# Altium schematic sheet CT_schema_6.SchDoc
size 521 x 498 mm
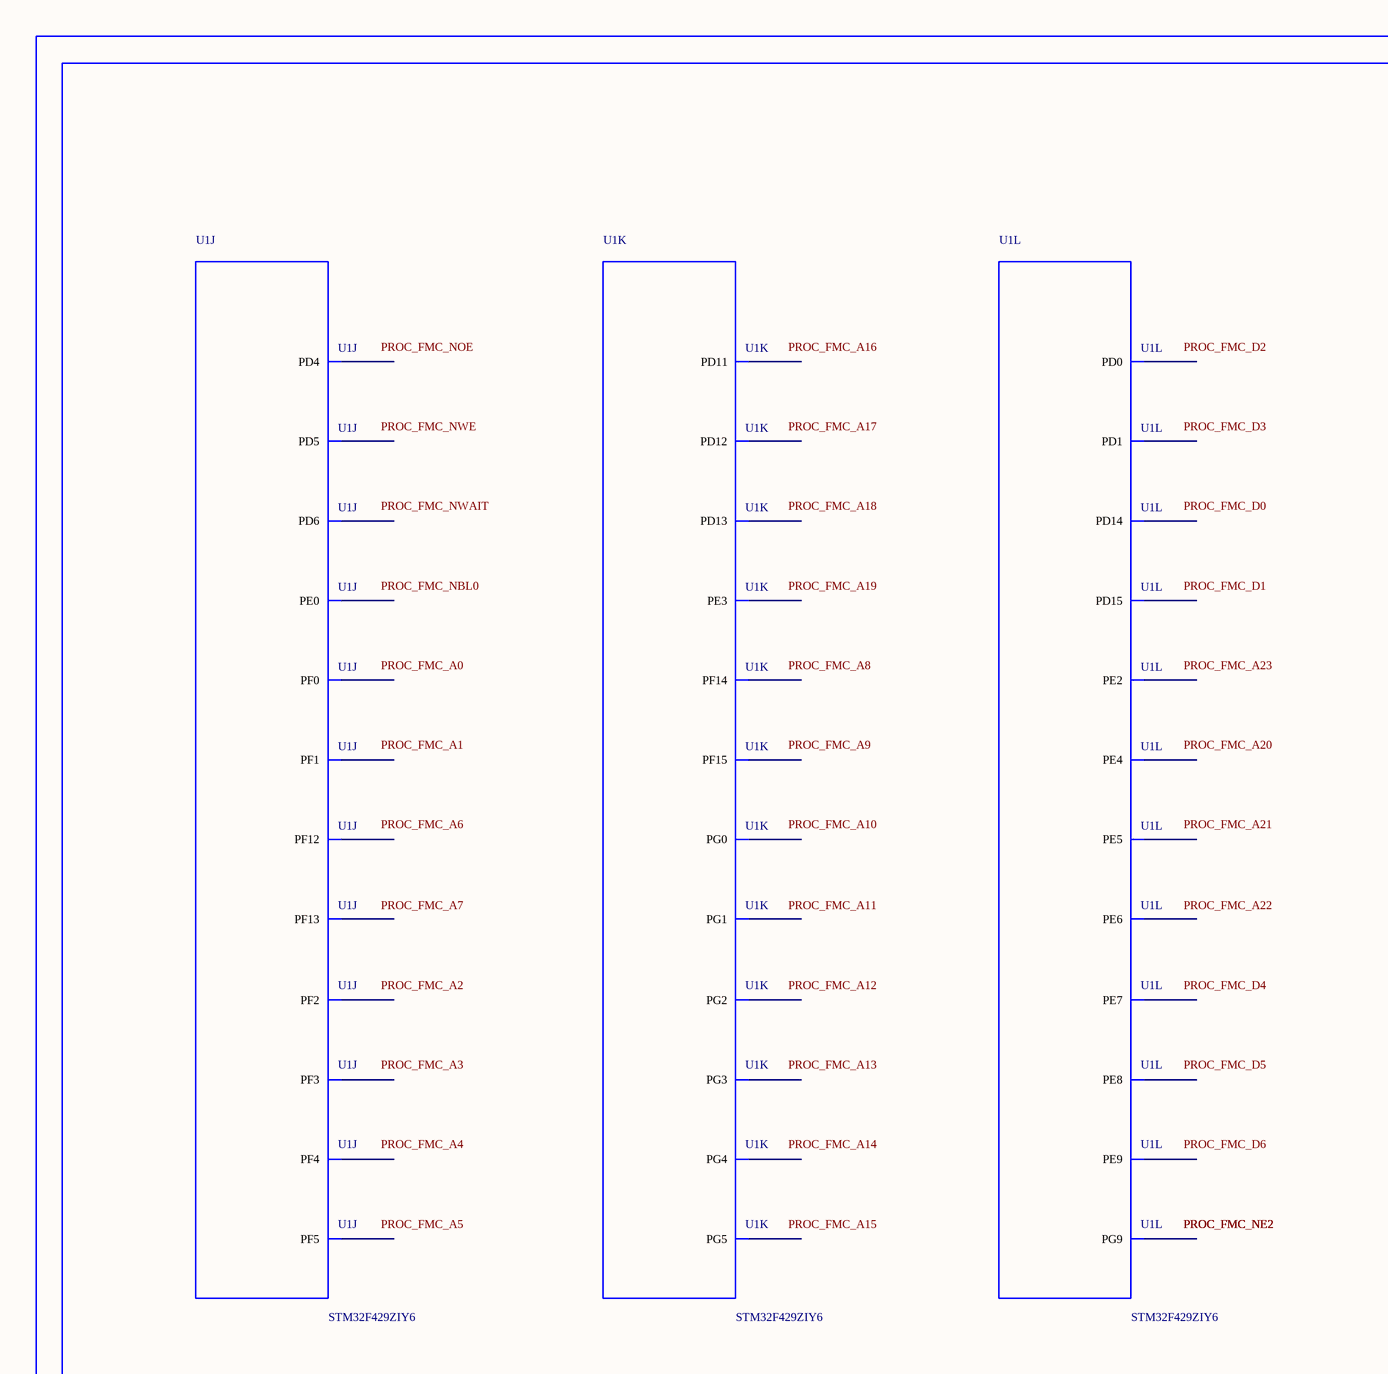
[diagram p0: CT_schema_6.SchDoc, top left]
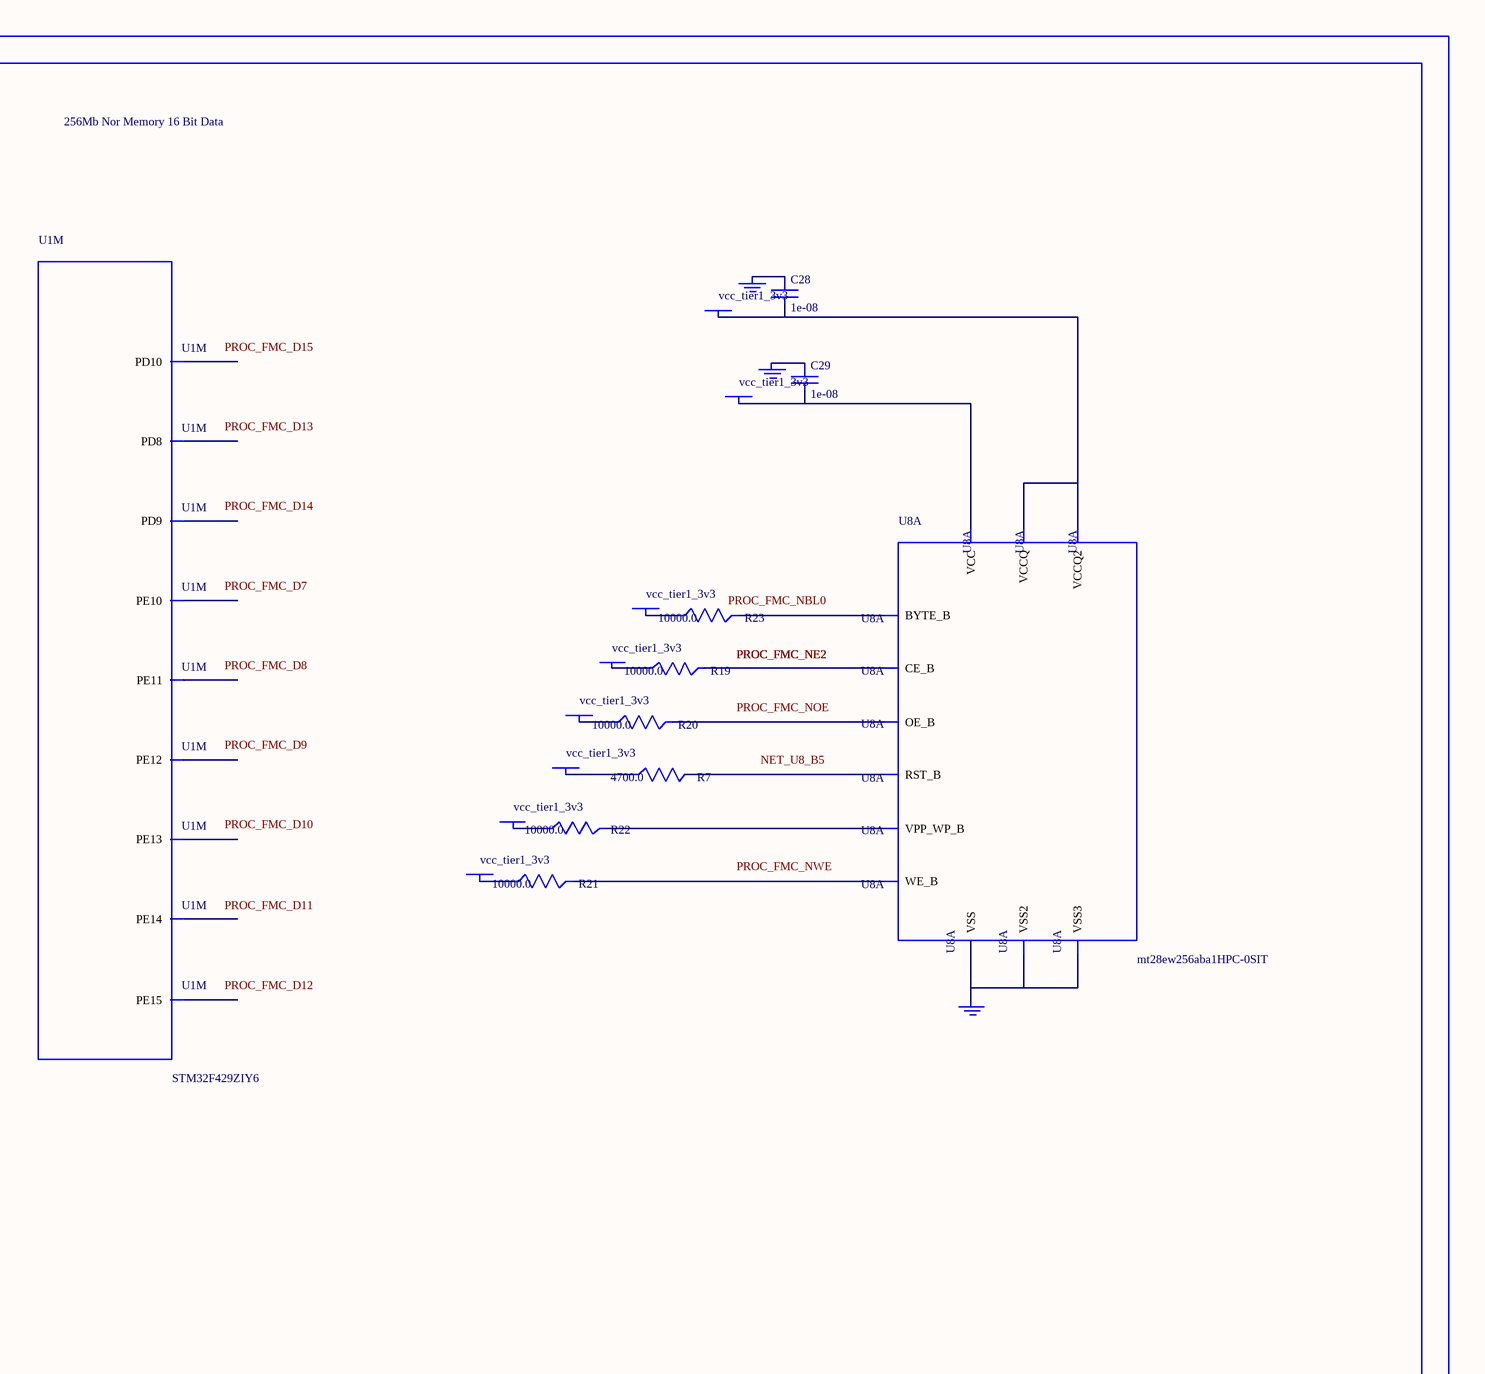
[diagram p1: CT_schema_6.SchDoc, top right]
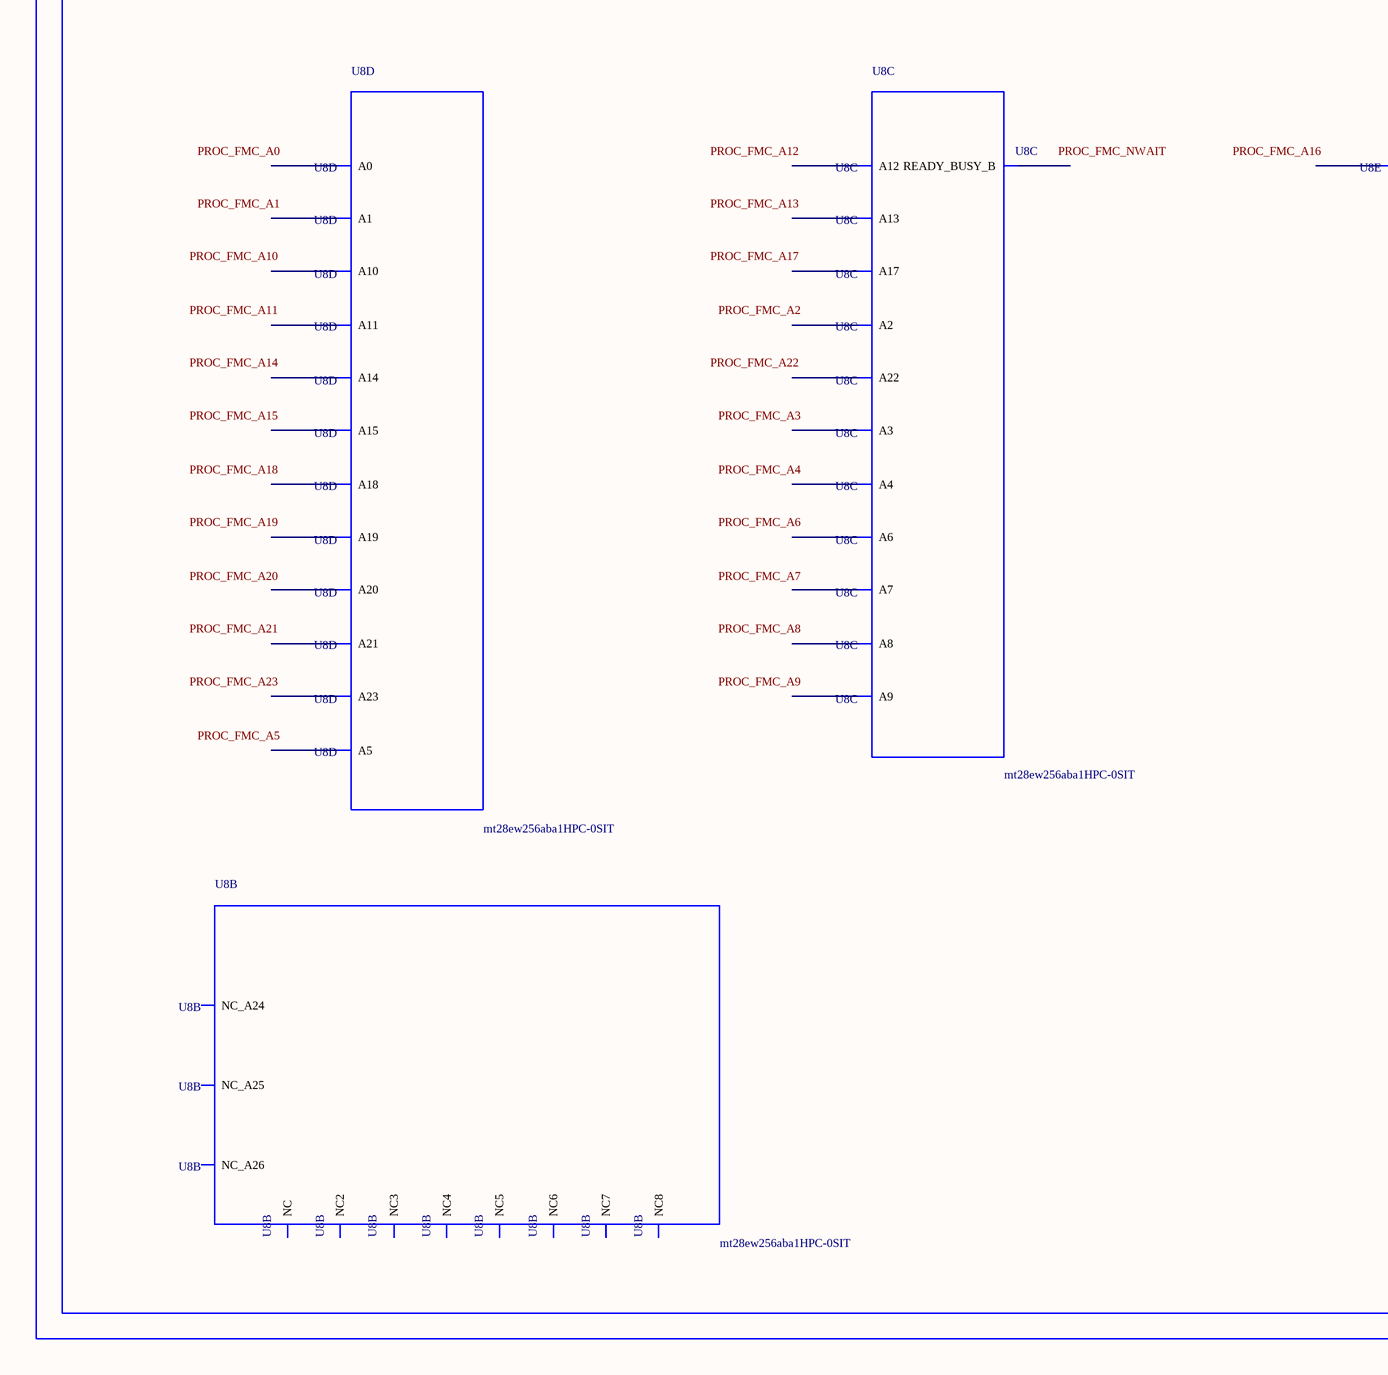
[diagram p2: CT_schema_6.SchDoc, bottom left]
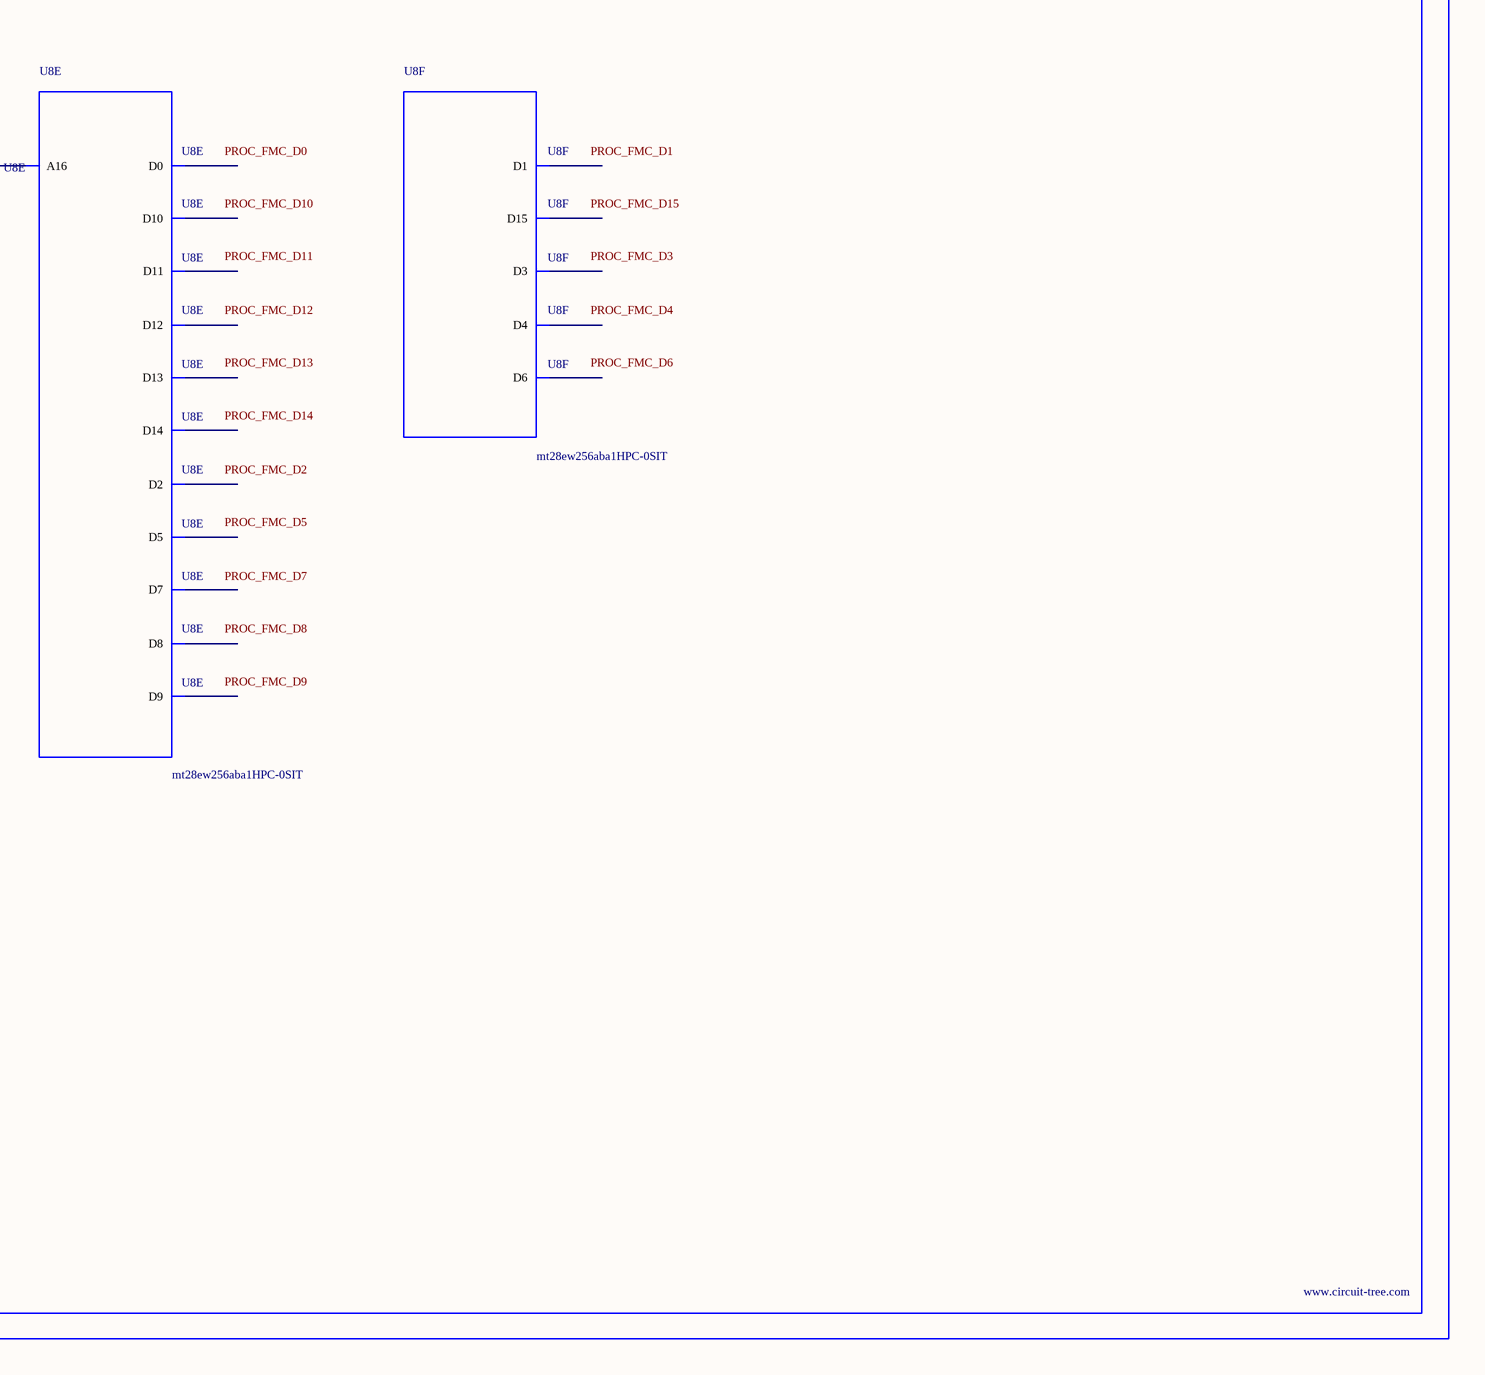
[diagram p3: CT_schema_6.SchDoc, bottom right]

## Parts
BORDER5  (no value)
C28  1e-08  [C0402]
C29  1e-08  [C0402]
GND_INSTANCE_5_0  (no value)
GND_INSTANCE_5_1  (no value)
GND_INSTANCE_5_2  (no value)
POWER_INSTANCE_5_0  vcc_tier1_3v3
POWER_INSTANCE_5_1  vcc_tier1_3v3
POWER_INSTANCE_5_2  vcc_tier1_3v3
POWER_INSTANCE_5_3  vcc_tier1_3v3
POWER_INSTANCE_5_4  vcc_tier1_3v3
POWER_INSTANCE_5_5  vcc_tier1_3v3
POWER_INSTANCE_5_6  vcc_tier1_3v3
POWER_INSTANCE_5_7  vcc_tier1_3v3
R7  4700.0  [R0603]
R19  10000.0  [R0603]
R20  10000.0  [R0603]
R21  10000.0  [R0603]
R22  10000.0  [R0603]
R23  10000.0  [R0603]
U1  STM32F429ZIY6  [WLCSP143]  (parts J,K,L,M of 13)
U8  mt28ew256aba1HPC-0SIT  [LBGA-64]  (parts A,B,C,D,E,F of 6)

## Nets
NetC28_1: C28.1 GND_INSTANCE_5_0.0(GND)
NetC28_2: C28.2 POWER_INSTANCE_5_0.0(PWR) U8.D8(VCCQ) U8.F1(VCCQ2)
NetC29_1: C29.1 GND_INSTANCE_5_1.0(GND)
NetC29_2: C29.2 POWER_INSTANCE_5_1.0(PWR) U8.G5(VCC)
NetGND_INSTANCE_5_2_0: GND_INSTANCE_5_2.0(GND) U8.E8(VSS) U8.H2(VSS2) U8.H7(VSS3)
NetPOWER_INSTANCE_5_2_0: POWER_INSTANCE_5_2.0(PWR) R19.1
NetPOWER_INSTANCE_5_3_0: POWER_INSTANCE_5_3.0(PWR) R20.1
NetPOWER_INSTANCE_5_4_0: POWER_INSTANCE_5_4.0(PWR) R21.1
NetPOWER_INSTANCE_5_5_0: POWER_INSTANCE_5_5.0(PWR) R22.1
NetPOWER_INSTANCE_5_6_0: POWER_INSTANCE_5_6.0(PWR) R23.1
NetPOWER_INSTANCE_5_7_0: POWER_INSTANCE_5_7.0(PWR) R7.1
NetR7_2: R7.2 U8.B5(RST_B)
NetR19_2: R19.2 U8.F2(CE_B)
NetR20_2: R20.2 U8.G2(OE_B)
NetR21_2: R21.2 U8.A5(WE_B)
NetR22_2: R22.2 U8.B4(VPP_WP_B)
NetR23_2: R23.2 U8.F7(BYTE_B)

Not connected (* = marked no-connect by the designer): U1 A4(PD5) B3(PD0) B5(PD4) B10(PE0) B11(PE4) C4(PD1) C10(PE3) D8(PE2) D9(PE5) E5(PG9) E8(PE6) E9(PF1) F4(PD6) F8(PF5) F9(PF4) F10(PF2) F11(PF0) G3(PG3) G5(PG4) G6(PG5) G11(PF3) H4(PD10) H5(PD13) H6(PD12) J1(PG2) J2(PD14) J4(PE10) K1(PD15) K2(PD11) K4(PE11) K5(PG1) K6(PF13) L2(PD8) L3(PE15) L4(PE12) L5(PE7) L6(PF14) M1(PD9) M4(PE14) M5(PE8) M6(PF15) N4(PE13) N5(PE9) N6(PG0) N7(PF12); U8 A1(NC) A2(A3) A3(A7) A4(READY_BUSY_B) A6(A9) A7(A13) A8(NC2) B1(NC_A26) B2(A4) B3(A17) B6(A8) B7(A12) B8(A22) C1(NC3) C2(A2) C3(A6) C4(A18) C5(A21) C6(A10) C7(A14) C8(A23) D1(NC4) D2(A1) D3(A5) D4(A20) D5(A19) D6(A11) D7(A15) E1(NC5) E2(A0) E3(D0) E4(D2) E5(D5) E6(D7) E7(A16) F3(D8) F4(D10) F5(D12) F6(D14) F8(NC_A24) G1(NC6) G3(D9) G4(D11) G6(D13) G7(D15) G8(NC_A25) H1(NC7) H3(D1) H4(D3) H5(D4) H6(D6) H8(NC8)

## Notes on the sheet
- Labels drawn without touching a wire or pin: NET_U8_B5, PROC_FMC_A0, PROC_FMC_A1, PROC_FMC_A2, PROC_FMC_A3, PROC_FMC_A4, PROC_FMC_A5, PROC_FMC_A6, PROC_FMC_A7, PROC_FMC_A8, PROC_FMC_A9, PROC_FMC_A10, PROC_FMC_A11, PROC_FMC_A12, PROC_FMC_A13, PROC_FMC_A14, PROC_FMC_A15, PROC_FMC_A16, PROC_FMC_A17, PROC_FMC_A18, PROC_FMC_A19, PROC_FMC_A20, PROC_FMC_A21, PROC_FMC_A22, PROC_FMC_A23, PROC_FMC_D0, PROC_FMC_D1, PROC_FMC_D2, PROC_FMC_D3, PROC_FMC_D4, PROC_FMC_D5, PROC_FMC_D6, PROC_FMC_D7, PROC_FMC_D8, PROC_FMC_D9, PROC_FMC_D10, PROC_FMC_D11, PROC_FMC_D12, PROC_FMC_D13, PROC_FMC_D14, PROC_FMC_D15, PROC_FMC_NBL0, PROC_FMC_NOE, PROC_FMC_NWAIT, PROC_FMC_NWE

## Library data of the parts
BORDER5 = BORDER_PAGE5
C28 C29 = C0402C103K3RAC
GND_INSTANCE_5_0-GND_INSTANCE_5_2 = GND
POWER_INSTANCE_5_0-POWER_INSTANCE_5_7 = PWR
R7 = RC0603JR-074K7L
R19-R23 = RC0603JR-0710KL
